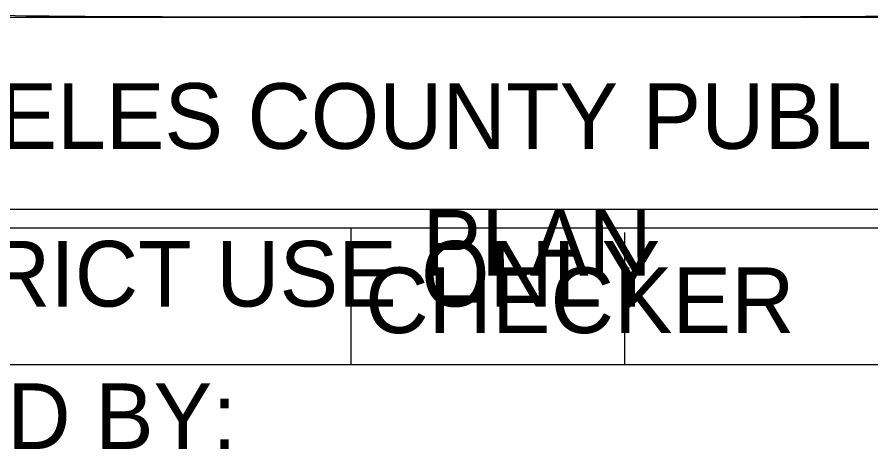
# Model space of a CAD drawing. Extents: x 837 to 1117, y 1316 to 1424.
# Drawn here: x 868.145 to 869.706, y 1400.427 to 1401.218 of the extents above; entities that cross this region are included whole.
import ezdxf

# ---------------------------------------------------------------- set-up
doc = ezdxf.new("R2010")
doc.units = 0
doc.layers.add('BASEMAP', color=7, linetype='Continuous')
doc.layers.add('LLINES', color=7, linetype='Continuous')

# ---------------------------------------------------------------- blocks, each defined once
blk = doc.blocks.new('_U1')
at = {"layer": 'LLINES'}
blk.add_line((-1.6222, -0.5907), (1.6237, -0.5907), dxfattribs=at)
blk.add_open_spline([(1.6237, -0.1737), (1.5983, -0.1738), (1.5491, -0.1739), (1.4571, -0.1888), (1.3294, -0.2187), (1.1518, -0.2794), (0.9561, -0.3425), (0.7506, -0.3705), (0.5779, -0.3926), (0.4178, -0.4012), (0.2906, -0.4008), (0.1563, -0.396), (0.0001, -0.3778), (-0.1826, -0.346), (-0.3534, -0.3102), (-0.4923, -0.2765), (-0.6042, -0.249), (-0.6984, -0.2398), (-0.7699, -0.2373), (-0.8303, -0.2385), (-0.9006, -0.2439), (-0.9843, -0.2576), (-1.0837, -0.2798), (-1.1773, -0.3031), (-1.27, -0.3237), (-1.3481, -0.3418), (-1.4221, -0.3516), (-1.497, -0.3622), (-1.5633, -0.3666), (-1.6073, -0.3674), (-1.6222, -0.3677), (-1.6222, -0.442), (-1.6222, -0.5164), (-1.6222, -0.5907), (-0.5402, -0.5907), (0.5418, -0.5907), (1.6237, -0.5907), (1.6237, -0.4517), (1.6237, -0.3127), (1.6237, -0.1737)], degree=3, dxfattribs=at)

msp = doc.modelspace()

# ---------------------------------------------------------------- linework, layer by layer
at = {"layer": 'BASEMAP'}
for p, q in [((870.7551, 1400.8665), (867.2551, 1400.8665)), ((870.7551, 1400.8323), (867.2551, 1400.8323)), ((868.7551, 1400.8323), (868.7551, 1400.5823)), ((869.2551, 1400.8244), (869.2551, 1400.5823)), ((870.7551, 1400.5823), (867.2551, 1400.5823))]:
    msp.add_line(p, q, dxfattribs=at)

# ---------------------------------------------------------------- block references
at = {"xscale": 0.7363891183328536, "yscale": 0.7363891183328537}
msp.add_blockref('_U1', (869.0051, 1401.653), dxfattribs=at)

# ---------------------------------------------------------------- texts
at = {"layer": 'LLINES'}
for s, p in [('LOS ANGELES COUNTY PUBLIC WORKS', (867.3978, 1400.9771)), ('PLAN', (868.8862, 1400.7452)), ('FOR DISTRICT USE ONLY', (867.3413, 1400.6888)), ('CHECKER', (868.7813, 1400.6403)), ('APPROVED BY:', (867.3514, 1400.4284))]:
    msp.add_text(s, height=0.12, dxfattribs=at).set_placement(p)

doc.saveas('drawing.dxf')
